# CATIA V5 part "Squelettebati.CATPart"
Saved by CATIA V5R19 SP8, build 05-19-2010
Part number: Squelettebati
Bounding box of the stored display mesh (mm): x -326.905 to 412.703, y 0 to 317.48, z 0 to 0
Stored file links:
  U:\Rendu_cfao_elguidj\Squelettebati.CATPart
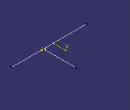
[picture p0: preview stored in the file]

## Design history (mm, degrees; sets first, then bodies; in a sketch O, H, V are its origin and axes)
Body1 (main body)
  Sketch1 on xy-plane, origin (0, 0, 0), H (1, 0, 0), V (0, 1, 0)
    line L1 (412.703, 0) -> (-326.9047, 0)
    point P1 (412.703, 0)
    line L2 (97.5248, 0) -> (97.5248, 317.48)
    point P3 (97.5248, 0)
    coincidence: P1 H, P3 L1
    horizontal: L1 H
    vertical: L2 V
